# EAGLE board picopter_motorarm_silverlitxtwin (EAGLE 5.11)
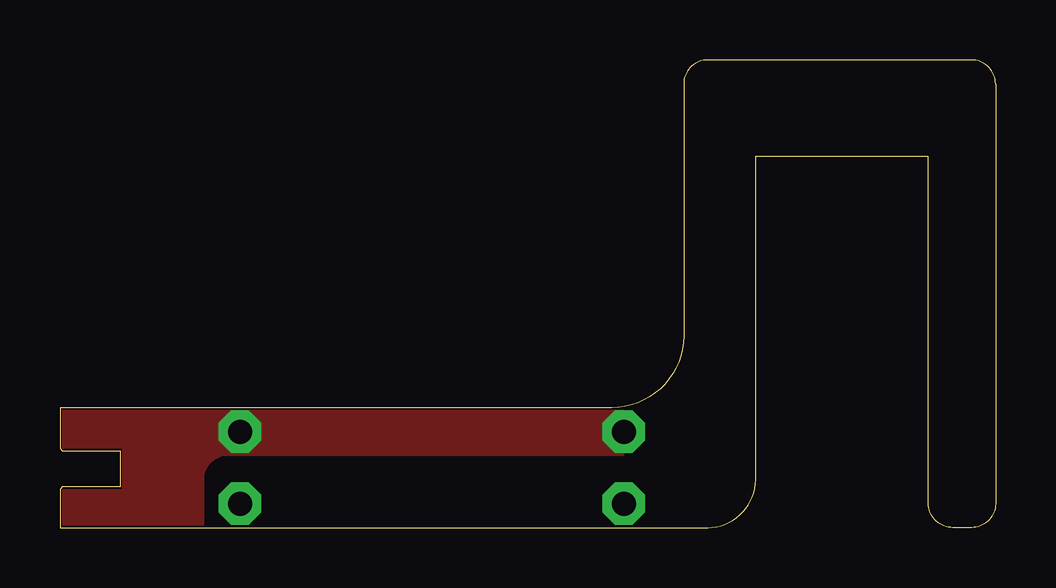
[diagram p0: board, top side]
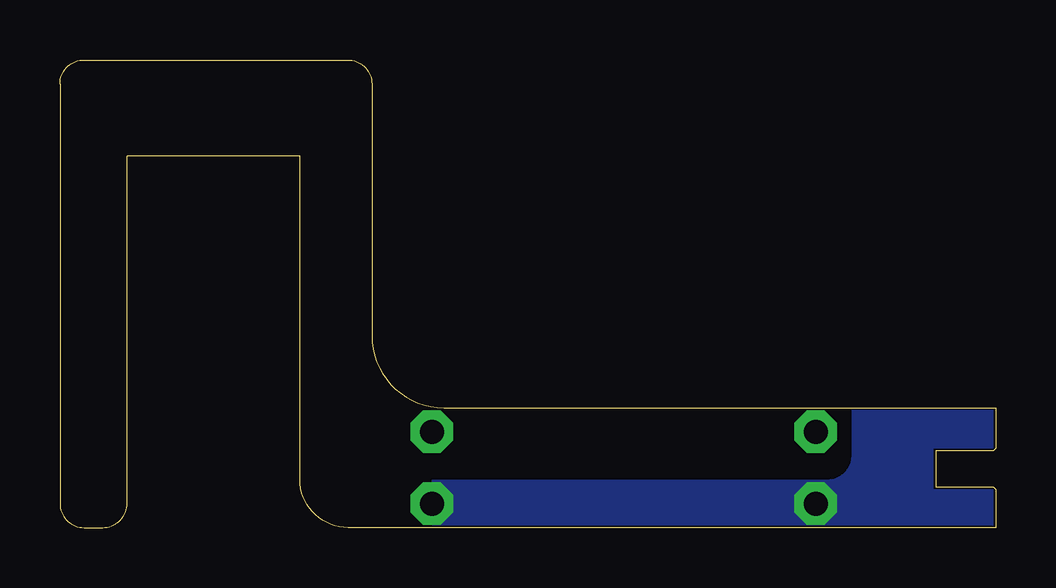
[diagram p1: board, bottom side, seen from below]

Size 39 x 19.5 mm. Coordinates in mm from the lower left corner, seen from the top.
Outline: 0,0 27,0 arc90 29,2 29,15.5 36.2,15.5 36.2,1.02 arc90 37.22,0 38,0 arc90 39,1 39,18.5 arc90 38,19.5 27,19.5 arc90 26,18.5 26,8 arc-90 23,5 0,5 0,3.3 0.1,3.2 2.5,3.2 2.5,1.7 0.1,1.7 0,1.6 0,0
Copper layers (1*16): Top 0.035mm / dielectric 1.5mm / Bottom 0.035mm
Design rules "default *": minimum track width 10mil, minimum drill 24mil, track to track 8mil, track to pad 8mil, pad to pad 8mil, via to via 8mil, smd to smd 8mil, copper to edge 0mil, drill to drill 8mil, minimum pad ring 10mil, minimum via ring 8mil, stop-mask expansion 4mil, vias tented up to drill 0mil, thermal gap 10mil

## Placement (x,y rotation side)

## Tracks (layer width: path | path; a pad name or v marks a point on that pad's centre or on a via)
S$9  (via drill 1 pad 1.78)
  other vias: 23.5,1 7.5,1
  pour Bottom: 0.1,0.1 23.5,0.1 23.5,2 7,2 arc-90 6,3 6,4.9 0.1,4.9 0.1,3.3 2.6,3.3 2.6,1.6 0.1,1.6
S$10  (via drill 1 pad 1.78)
  other vias: 23.5,4 7.5,4
  pour Top: 0.1,4.9 23.5,4.9 23.5,3 7,3 arc90 6,2 6,0.1 0.1,0.1 0.1,1.6 2.6,1.6 2.6,3.3 0.1,3.3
